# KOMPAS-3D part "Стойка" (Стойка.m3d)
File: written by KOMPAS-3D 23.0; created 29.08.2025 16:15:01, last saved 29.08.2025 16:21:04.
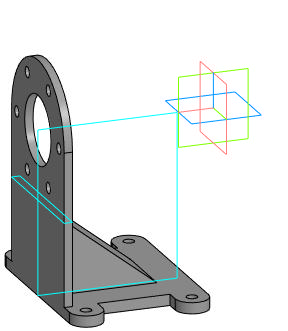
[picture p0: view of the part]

Document properties: Автор: Inspektor_Kot; Полное имя файла: I:\Autodesk Inventor Projects\ИМ-ИТ ЦД\Вариант 4\Стойка.m3d

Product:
- Part/product: Стойка
    Масса: 2.086013

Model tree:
1. Эскиз:1  (with: Элемент вращения:1, Элемент выдавливания:1, Элемент выдавливания:2)
2. Элемент выдавливания:1
     Расстояние 1 = 6
3. Касательная плоскость:1  (with: Элемент выдавливания:1)
4. Эскиз:2  (with: Элемент выдавливания:1)
5. Элемент выдавливания:2
     Расстояние 2 = 60
6. Эскиз:3  (with: Элемент выдавливания:2)
7. Элемент выдавливания:3
     Расстояние 1 = 8
8. Элемент выдавливания:4  (with: Элемент выдавливания:2, Элемент выдавливания:1)
9. Эскиз:4  (with: Элемент выдавливания:3)
10. Элемент выдавливания:5
     Расстояние 2 = 8
11. Массив по сетке:1  (with: Элемент выдавливания:5, Эскиз:4, Элемент выдавливания:3)  (2 pattern instances)
     Шаг 1 = 76; Угол раствора = 90
12. Средняя плоскость:1  (with: Элемент выдавливания:2)
13. Зеркальный массив:1
14. Экземпляр ( 1 )
15. Экземпляр ( 2 )  (with: Массив по сетке:1, Экземпляр ( 1 ), Элемент выдавливания:5)
16. Эскиз:5  (with: Элемент выдавливания:2, Элемент выдавливания:5)
17. Ребро жесткости:1
     Толщина стенки 1 = 50; Толщина стенки 2 = 1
